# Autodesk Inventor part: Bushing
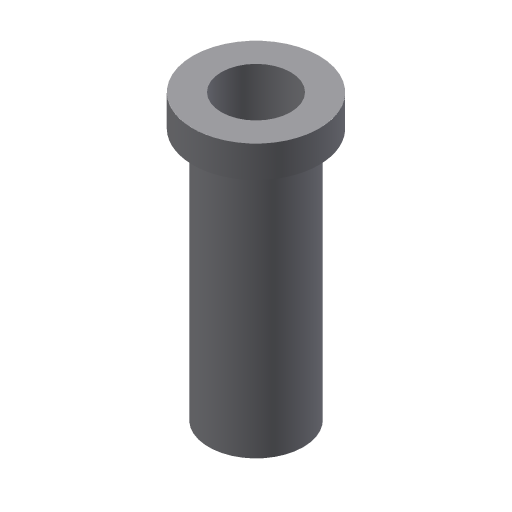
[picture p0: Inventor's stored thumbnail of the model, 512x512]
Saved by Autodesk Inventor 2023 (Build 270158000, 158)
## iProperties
Created: 2002-02
Part Number: Bushing
Document SubType Name: Modeling
Designer: ***
Density: 1 g/cm^3
Material: Generic
Appearance: Default
Control State: 0
Master: False
Checked Out: False
Shininess: 77.0
Length Units: 11269
Angle Units: 11279
Time Units: 11290
Mass Units: 11283
Length Display Precision: 3
Angle Display Precision: 2
Density: 0.0
Volumn: 0.0
Area: 0.0
PropertySet Name: Model Information
Author: ***
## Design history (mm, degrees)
sketch "Sketch2"
  geometry: C1 r 10 at (0, 0); 1 further point
  constraints: 1 centre point, 1 coincident
  dimensions: "d8" = 20 diameter of C1
extrude "Extrusion1" new body sketch "Sketch2" distance "d6" = 5; taper "d7" = 0 deg
sketch "Sketch4"
  geometry: C1 r 7.5 at (0, 0); 1 further point
  constraints: 1 centre point, 1 coincident
  dimensions: "d9" = 15 diameter of C1
extrude "Extrusion2" join sketch "Sketch4" distance "d10" = 40; taper "d11" = 0 deg
sketch "Sketch5"
  geometry: C1 r 5.5 at (0, 0); 1 further point
  constraints: 1 centre point, 1 coincident
  dimensions: "d12" = 11 diameter of C1
extrude "Extrusion3" cut sketch "Sketch5" distance "d13" = 57.75; taper "d14" = 0 deg
body "Solid2"
